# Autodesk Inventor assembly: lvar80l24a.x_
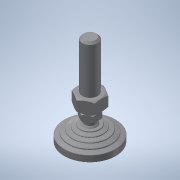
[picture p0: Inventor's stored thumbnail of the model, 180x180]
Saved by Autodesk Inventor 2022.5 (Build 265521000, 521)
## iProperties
Part Number: lvar80l24a.x_
Material: 一般
Document SubType Name: Assembly
Designer: ImaoCorp
Sending System: SOLIDWORKS 2017-2017317
MC: AMD64
MC_MODEL: Intel64 Family 6 Model 60 Stepping 3, GenuineIntel
OS: Windows_NT
FRU: Parasolid Version 29.0, build 201,  4-17-2017
FORMAT: text
GUISE: transmit
KEY: lvar80l24a
FILE: lvar80l24a.x_t
DATE: Mon Jul 01 18:15:10 2019
Author: ImaoCorp
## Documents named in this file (3)
- X:\14_SW2022-Inv2022\00_全2023-1023新製品(TCC)まで\l\lvar80l24a\LVAR80L24A.iam
- X:\14_SW2022-Inv2022\00_全2023-1023新製品(TCC)まで\l\lvar80l24a\lvar80l24a_01.ipt
- X:\14_SW2022-Inv2022\00_全2023-1023新製品(TCC)まで\l\lvar80l24a\lvar80l24a_02.ipt
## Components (2 placed, 2 different names)
1. lvar80l24a_01
2. lvar80l24a_02
